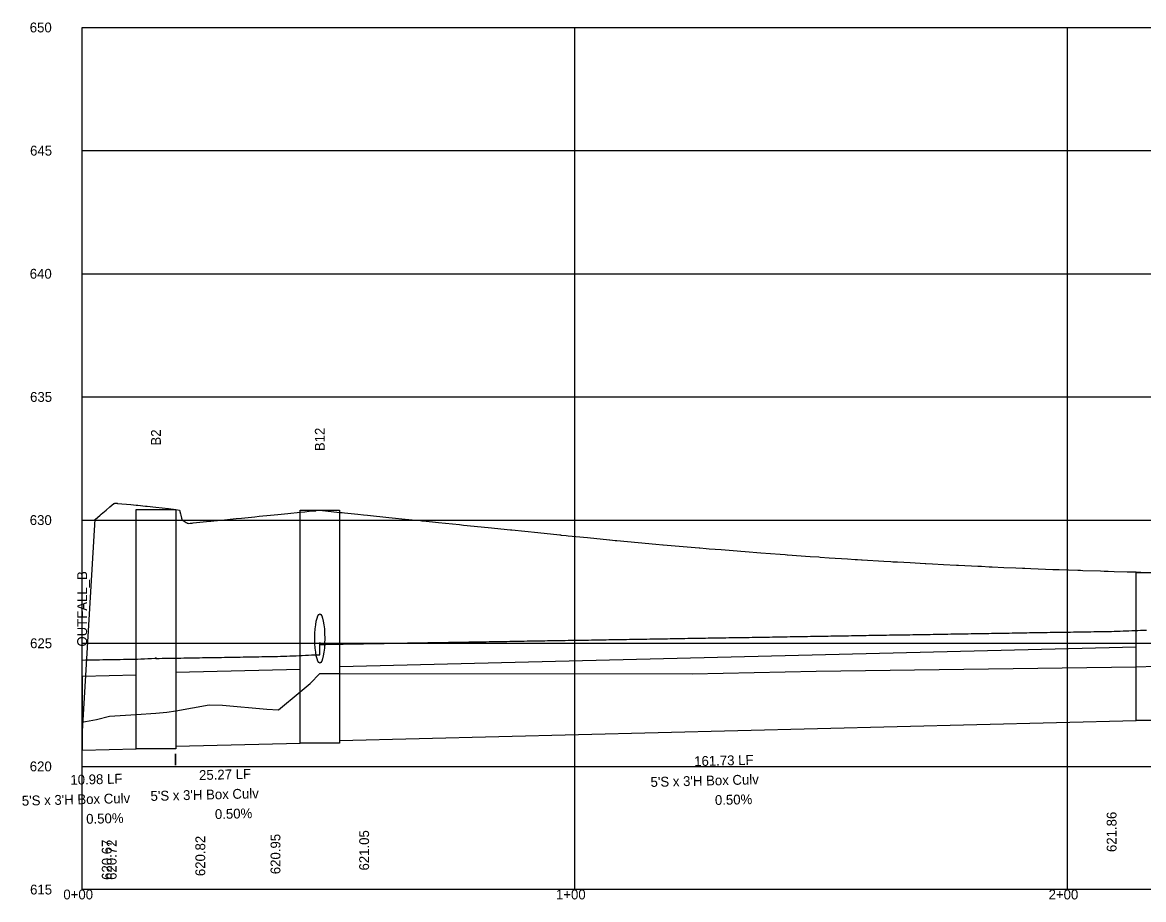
# Model space of a CAD drawing. Extents: x 2253035 to 2279930, y 13774972 to 13793443.
# Drawn here: x 2260014.3 to 2260241.9, y 13791296.5 to 13791474.6 of the extents above; entities that cross this region are included whole.
import ezdxf

# ---------------------------------------------------------------- set-up
doc = ezdxf.new("R2010")
doc.units = 0
for name, color, linetype in [('Default', 7, 'Continuous'), ('E_Utility_ATT_HH', 7, 'Continuous'), ('E_Utility_ATT_PR_PVC', 7, 'Continuous'), ('E_Utillity_Water_Water Line_12in', 7, 'Continuous'), ('E_Utillity_Water_Water Line_1in', 7, 'Continuous'), ('E_Utillity_Water_Water Line_4in', 7, 'Continuous'), ('E_Utillity_Water_Water Line_8in', 7, 'Continuous')]:
    doc.layers.add(name, color=color, linetype=linetype)

msp = doc.modelspace()

# ---------------------------------------------------------------- linework, layer by layer
at = {"layer": 'Default'}
for p, q in [((2260126.46, 13791298.56), (2260126.46, 13791473.56)), ((2260226.46, 13791298.56), (2260226.46, 13791473.56)), ((2260026.46, 13791448.56), (2261320.64, 13791448.56)), ((2260026.46, 13791423.56), (2261320.64, 13791423.56)), ((2260026.46, 13791398.56), (2261320.64, 13791398.56)), ((2260026.46, 13791373.56), (2261320.64, 13791373.56)), ((2260026.46, 13791348.56), (2261320.64, 13791348.56)), ((2260026.46, 13791323.56), (2261320.64, 13791323.56))]:
    msp.add_line(p, q, dxfattribs=at)
msp.add_lwpolyline([(2260026.46, 13791298.56), (2260026.46, 13791473.56), (2261320.64, 13791473.56), (2261320.64, 13791298.56)], close=True, dxfattribs=at)
at = {"layer": 'E_Utility_ATT_PR_PVC'}
for p, q in [((2260074.71, 13791348.72), (2260074.71, 13791348.32)), ((2260041.45, 13791345.68), (2260041.45, 13791345.48))]:
    msp.add_line(p, q, dxfattribs=at)
for points in [[(2260074.71, 13791348.32), (2260075.31, 13791348.33), (2260075.9, 13791348.34), (2260076.49, 13791348.35), (2260077.09, 13791348.36), (2260077.68, 13791348.37), (2260078.27, 13791348.38), (2260078.86, 13791348.39), (2260079.46, 13791348.4), (2260080.05, 13791348.41), (2260080.64, 13791348.42), (2260081.24, 13791348.43), (2260081.83, 13791348.44), (2260082.42, 13791348.45), (2260083.01, 13791348.46), (2260083.61, 13791348.47), (2260084.2, 13791348.48), (2260084.79, 13791348.49), (2260085.39, 13791348.5), (2260085.98, 13791348.51), (2260086.57, 13791348.52), (2260087.16, 13791348.53), (2260087.76, 13791348.54), (2260088.35, 13791348.55), (2260088.94, 13791348.56), (2260089.54, 13791348.57), (2260090.13, 13791348.58), (2260090.72, 13791348.59), (2260091.32, 13791348.6), (2260091.91, 13791348.61), (2260092.5, 13791348.62), (2260093.09, 13791348.62), (2260093.69, 13791348.63), (2260094.28, 13791348.64), (2260094.87, 13791348.65), (2260095.47, 13791348.66), (2260096.06, 13791348.67), (2260096.65, 13791348.68), (2260097.24, 13791348.69), (2260097.84, 13791348.7), (2260098.43, 13791348.71), (2260099.02, 13791348.72), (2260099.62, 13791348.73), (2260100.21, 13791348.74), (2260100.8, 13791348.75), (2260101.39, 13791348.76), (2260101.99, 13791348.77), (2260102.58, 13791348.78), (2260103.17, 13791348.79), (2260103.77, 13791348.8), (2260104.36, 13791348.81), (2260104.95, 13791348.82), (2260105.55, 13791348.83), (2260106.14, 13791348.84), (2260106.73, 13791348.85), (2260107.32, 13791348.86), (2260107.92, 13791348.87), (2260108.51, 13791348.88), (2260109.1, 13791348.89), (2260109.7, 13791348.9), (2260110.29, 13791348.91), (2260110.88, 13791348.92), (2260111.47, 13791348.93), (2260112.07, 13791348.94), (2260112.66, 13791348.95), (2260113.25, 13791348.96), (2260113.85, 13791348.97), (2260114.44, 13791348.98), (2260115.03, 13791348.99), (2260115.62, 13791349), (2260116.22, 13791349.01), (2260116.81, 13791349.02), (2260117.4, 13791349.03), (2260118, 13791349.04), (2260118.59, 13791349.05), (2260119.18, 13791349.06), (2260119.78, 13791349.07), (2260120.37, 13791349.08), (2260120.96, 13791349.09), (2260121.55, 13791349.1), (2260122.15, 13791349.11), (2260122.74, 13791349.12), (2260123.33, 13791349.13), (2260123.93, 13791349.14), (2260124.52, 13791349.15), (2260125.11, 13791349.16), (2260125.7, 13791349.17), (2260126.3, 13791349.17), (2260126.89, 13791349.18), (2260127.48, 13791349.19), (2260128.08, 13791349.2), (2260128.67, 13791349.21), (2260129.26, 13791349.22), (2260129.85, 13791349.23), (2260130.45, 13791349.24), (2260131.04, 13791349.25), (2260131.63, 13791349.26), (2260132.23, 13791349.27), (2260132.82, 13791349.28), (2260133.41, 13791349.29), (2260134.01, 13791349.3), (2260134.6, 13791349.31), (2260135.19, 13791349.32), (2260135.78, 13791349.33), (2260136.38, 13791349.34), (2260136.97, 13791349.35), (2260137.56, 13791349.36), (2260138.16, 13791349.37), (2260138.75, 13791349.38), (2260139.34, 13791349.39), (2260139.93, 13791349.4), (2260140.53, 13791349.41), (2260141.12, 13791349.42), (2260141.71, 13791349.43), (2260142.31, 13791349.44), (2260142.9, 13791349.45), (2260143.49, 13791349.46), (2260144.08, 13791349.47), (2260144.68, 13791349.48), (2260145.27, 13791349.49), (2260145.86, 13791349.5), (2260146.46, 13791349.51), (2260147.05, 13791349.52), (2260147.64, 13791349.53), (2260148.24, 13791349.54), (2260148.83, 13791349.55), (2260149.42, 13791349.56), (2260150.01, 13791349.57), (2260150.61, 13791349.58), (2260151.2, 13791349.59), (2260151.79, 13791349.6), (2260152.39, 13791349.61), (2260152.98, 13791349.62), (2260153.57, 13791349.63), (2260154.16, 13791349.64), (2260154.76, 13791349.65), (2260155.35, 13791349.66), (2260155.94, 13791349.67), (2260156.54, 13791349.68), (2260157.13, 13791349.69), (2260157.72, 13791349.7), (2260158.31, 13791349.71), (2260158.91, 13791349.72), (2260159.5, 13791349.73), (2260160.09, 13791349.73), (2260160.69, 13791349.74), (2260161.28, 13791349.75), (2260161.87, 13791349.76), (2260162.47, 13791349.77), (2260163.06, 13791349.78), (2260163.65, 13791349.79), (2260164.24, 13791349.8), (2260164.84, 13791349.81), (2260165.43, 13791349.82), (2260166.02, 13791349.83), (2260166.62, 13791349.84), (2260167.21, 13791349.85), (2260167.8, 13791349.86), (2260168.39, 13791349.87), (2260168.99, 13791349.88), (2260169.58, 13791349.89), (2260170.17, 13791349.9), (2260170.77, 13791349.91), (2260171.36, 13791349.92), (2260171.95, 13791349.93), (2260172.54, 13791349.94), (2260173.14, 13791349.95), (2260173.73, 13791349.96), (2260174.32, 13791349.97), (2260174.92, 13791349.98), (2260175.51, 13791349.99), (2260176.1, 13791350), (2260176.7, 13791350.01), (2260177.29, 13791350.02), (2260177.88, 13791350.03), (2260178.47, 13791350.04), (2260179.07, 13791350.05), (2260179.66, 13791350.06), (2260180.25, 13791350.07), (2260180.85, 13791350.08), (2260181.44, 13791350.09), (2260182.03, 13791350.1), (2260182.62, 13791350.11), (2260183.22, 13791350.12), (2260183.81, 13791350.13), (2260184.4, 13791350.14), (2260185, 13791350.15), (2260185.59, 13791350.16), (2260186.18, 13791350.17), (2260186.77, 13791350.18), (2260187.37, 13791350.19), (2260187.96, 13791350.2), (2260188.55, 13791350.21), (2260189.15, 13791350.22), (2260189.74, 13791350.23), (2260190.33, 13791350.24), (2260190.93, 13791350.25), (2260191.52, 13791350.26), (2260192.11, 13791350.27), (2260192.7, 13791350.28), (2260193.3, 13791350.28), (2260193.89, 13791350.29), (2260194.48, 13791350.3), (2260195.08, 13791350.31), (2260195.67, 13791350.32), (2260196.26, 13791350.33), (2260196.85, 13791350.34), (2260197.45, 13791350.35), (2260198.04, 13791350.36), (2260198.63, 13791350.37), (2260199.23, 13791350.38), (2260199.82, 13791350.39), (2260200.41, 13791350.4), (2260201, 13791350.41), (2260201.6, 13791350.42), (2260202.19, 13791350.43), (2260202.78, 13791350.44), (2260203.38, 13791350.45), (2260203.97, 13791350.46), (2260204.56, 13791350.47), (2260205.16, 13791350.48), (2260205.75, 13791350.49), (2260206.34, 13791350.5), (2260206.93, 13791350.51), (2260207.53, 13791350.52), (2260208.12, 13791350.53), (2260208.71, 13791350.54), (2260209.31, 13791350.55), (2260209.9, 13791350.56), (2260210.49, 13791350.57), (2260211.08, 13791350.58), (2260211.68, 13791350.59), (2260212.27, 13791350.6), (2260212.86, 13791350.61), (2260213.46, 13791350.62), (2260214.05, 13791350.63), (2260214.64, 13791350.64), (2260215.23, 13791350.65), (2260215.83, 13791350.66), (2260216.42, 13791350.67), (2260217.01, 13791350.68), (2260217.61, 13791350.69), (2260218.2, 13791350.7), (2260218.79, 13791350.71), (2260219.39, 13791350.72), (2260219.98, 13791350.73), (2260220.57, 13791350.74), (2260221.16, 13791350.75), (2260221.76, 13791350.76), (2260222.35, 13791350.77), (2260222.94, 13791350.78), (2260223.54, 13791350.79), (2260224.13, 13791350.8), (2260224.72, 13791350.81), (2260225.31, 13791350.82), (2260225.91, 13791350.83), (2260226.5, 13791350.84), (2260227.09, 13791350.84), (2260227.69, 13791350.85), (2260228.28, 13791350.86), (2260228.87, 13791350.87), (2260229.46, 13791350.88), (2260230.06, 13791350.89), (2260230.65, 13791350.9), (2260231.24, 13791350.91), (2260231.84, 13791350.92), (2260232.43, 13791350.93), (2260233.02, 13791350.94), (2260233.62, 13791350.95), (2260234.21, 13791350.96), (2260234.8, 13791350.97), (2260235.39, 13791350.98), (2260235.99, 13791350.99), (2260236.58, 13791351.01), (2260237.17, 13791351.03), (2260237.77, 13791351.05), (2260238.36, 13791351.08), (2260238.95, 13791351.1), (2260239.54, 13791351.13), (2260240.14, 13791351.15), (2260240.73, 13791351.18), (2260241.32, 13791351.2), (2260241.92, 13791351.23), (2260242.51, 13791351.25)], [(2260041.45, 13791345.48), (2260042.08, 13791345.49), (2260042.71, 13791345.5), (2260043.34, 13791345.51), (2260043.97, 13791345.52), (2260044.61, 13791345.53), (2260045.24, 13791345.54), (2260045.87, 13791345.55), (2260046.5, 13791345.56), (2260047.13, 13791345.58), (2260047.76, 13791345.59), (2260048.4, 13791345.6), (2260049.03, 13791345.61), (2260049.66, 13791345.62), (2260050.29, 13791345.63), (2260050.92, 13791345.64), (2260051.56, 13791345.65), (2260052.19, 13791345.66), (2260052.82, 13791345.67), (2260053.45, 13791345.68), (2260054.08, 13791345.69), (2260054.72, 13791345.7), (2260055.35, 13791345.72), (2260055.98, 13791345.73), (2260056.61, 13791345.74), (2260057.24, 13791345.75), (2260057.88, 13791345.76), (2260058.51, 13791345.77), (2260059.14, 13791345.78), (2260059.77, 13791345.79), (2260060.4, 13791345.8), (2260061.04, 13791345.81), (2260061.67, 13791345.82), (2260062.3, 13791345.83), (2260062.93, 13791345.84), (2260063.56, 13791345.86), (2260064.19, 13791345.87), (2260064.83, 13791345.88), (2260065.46, 13791345.89), (2260066.09, 13791345.9), (2260066.72, 13791345.91), (2260067.35, 13791345.94), (2260067.99, 13791345.96), (2260068.62, 13791345.99), (2260069.25, 13791346.02), (2260069.88, 13791346.04), (2260070.51, 13791346.07), (2260071.15, 13791346.1), (2260071.78, 13791346.12), (2260072.41, 13791346.15), (2260073.04, 13791346.18), (2260073.67, 13791346.2), (2260074.31, 13791346.23), (2260074.71, 13791346.24), (2260074.71, 13791348.72)], [(2260026.46, 13791345.16), (2260027.16, 13791345.17), (2260027.86, 13791345.18), (2260028.57, 13791345.19), (2260029.27, 13791345.21), (2260029.97, 13791345.22), (2260030.68, 13791345.23), (2260031.38, 13791345.24), (2260032.08, 13791345.26), (2260032.78, 13791345.27), (2260033.49, 13791345.28), (2260034.19, 13791345.29), (2260034.89, 13791345.31), (2260035.6, 13791345.32), (2260036.3, 13791345.33), (2260037, 13791345.35), (2260037.71, 13791345.36), (2260038.41, 13791345.39), (2260039.11, 13791345.42), (2260039.82, 13791345.45), (2260040.52, 13791345.49), (2260041.22, 13791345.52), (2260041.45, 13791345.52), (2260041.45, 13791345.68)]]:
    msp.add_lwpolyline(points, dxfattribs=at)
at = {"layer": 'E_Utillity_Water_Water Line_12in'}
for points in [[(2260037.45, 13791375.69), (2260045.45, 13791375.69), (2260045.45, 13791327.16), (2260037.45, 13791327.16)], [(2260070.71, 13791375.55), (2260078.71, 13791375.55), (2260078.71, 13791328.31), (2260070.71, 13791328.31)], [(2260240.44, 13791362.93), (2260248.44, 13791362.93), (2260248.44, 13791332.86), (2260240.44, 13791332.86)], [(2260026.46, 13791341.86), (2260026.46, 13791341.86), (2260026.46, 13791326.88), (2260026.46, 13791326.88)], [(2260045.41, 13791326.09), (2260045.41, 13791326.09), (2260045.41, 13791323.78), (2260045.41, 13791323.78)]]:
    msp.add_lwpolyline(points, close=True, dxfattribs=at)
at = {"layer": 'E_Utillity_Water_Water Line_1in'}
msp.add_lwpolyline([(2260026.46, 13791332.58), (2260026.46, 13791332.58), (2260026.46, 13791332.58), (2260027.15, 13791332.71), (2260029.39, 13791333.06), (2260032.04, 13791333.77), (2260037.45, 13791334.13), (2260037.45, 13791334.13), (2260041.45, 13791334.39), (2260041.45, 13791334.39), (2260043.66, 13791334.54), (2260045.45, 13791334.85), (2260045.45, 13791334.85), (2260052.27, 13791336.06), (2260054.98, 13791335.98), (2260063.97, 13791335.16), (2260066.35, 13791335.06), (2260070.71, 13791338.69), (2260070.71, 13791338.69), (2260072.75, 13791340.38), (2260074.71, 13791342.43), (2260074.71, 13791342.43), (2260078.71, 13791342.4), (2260078.71, 13791342.4), (2260150.29, 13791342.38), (2260175.47, 13791342.91), (2260240.44, 13791343.79), (2260240.44, 13791343.79), (2260244.44, 13791343.93)], dxfattribs=at)
at = {"layer": 'E_Utillity_Water_Water Line_4in'}
for p, q in [((2260078.71, 13791343.81), (2260240.44, 13791347.86)), ((2260045.45, 13791342.67), (2260070.71, 13791343.31)), ((2260026.46, 13791341.88), (2260037.45, 13791342.16)), ((2260078.71, 13791328.81), (2260240.44, 13791332.86)), ((2260026.46, 13791326.88), (2260037.45, 13791327.16)), ((2260045.45, 13791327.67), (2260070.71, 13791328.31))]:
    msp.add_line(p, q, dxfattribs=at)
msp.add_ellipse((2260074.71, 13791349.53), major_axis=(0, 5), ratio=0.2, dxfattribs=at)
at = {"layer": 'E_Utillity_Water_Water Line_8in'}
msp.add_lwpolyline([(2260026.46, 13791329.56), (2260026.46, 13791329.56), (2260026.46, 13791329.56), (2260029.12, 13791373.73), (2260029.12, 13791373.73), (2260029.15, 13791373.75), (2260029.17, 13791373.77), (2260029.56, 13791374.1), (2260030.11, 13791374.56), (2260030.34, 13791374.75), (2260031.31, 13791375.56), (2260032.11, 13791376.22), (2260032.51, 13791376.56), (2260032.92, 13791376.9), (2260032.98, 13791376.95), (2260033, 13791376.96), (2260033.06, 13791377.02), (2260033.54, 13791376.97), (2260033.64, 13791376.96), (2260036.34, 13791376.7), (2260037.45, 13791376.59), (2260037.45, 13791376.59), (2260037.79, 13791376.56), (2260039.34, 13791376.4), (2260039.54, 13791376.38), (2260039.68, 13791376.36), (2260041.42, 13791376.18), (2260041.45, 13791376.18), (2260041.45, 13791376.18), (2260042.69, 13791376.05), (2260044.01, 13791375.91), (2260045.45, 13791375.69), (2260045.45, 13791375.69), (2260046.25, 13791375.56), (2260046.43, 13791374.85), (2260046.51, 13791374.56), (2260046.66, 13791373.98), (2260046.71, 13791373.78), (2260046.77, 13791373.56), (2260046.92, 13791373.47), (2260047.19, 13791373.31), (2260047.59, 13791373.08), (2260047.73, 13791373), (2260047.73, 13791373), (2260047.8, 13791372.96), (2260047.85, 13791372.93), (2260047.86, 13791372.93), (2260047.89, 13791372.91), (2260047.96, 13791372.87), (2260048.41, 13791372.92), (2260048.5, 13791372.93), (2260048.8, 13791372.96), (2260048.83, 13791372.96), (2260049.01, 13791372.98), (2260052.4, 13791373.32), (2260052.51, 13791373.33), (2260052.57, 13791373.34), (2260053.22, 13791373.4), (2260054.76, 13791373.56), (2260057.75, 13791373.86), (2260058.8, 13791373.96), (2260061.52, 13791374.24), (2260062.43, 13791374.33), (2260064.71, 13791374.56), (2260066.21, 13791374.71), (2260068.22, 13791374.91), (2260070.71, 13791375.16), (2260070.71, 13791375.16), (2260071.64, 13791375.25), (2260072.55, 13791375.34), (2260073.57, 13791375.44), (2260073.9, 13791375.47), (2260073.97, 13791375.48), (2260074.71, 13791375.55), (2260074.71, 13791375.55), (2260078.71, 13791375.13), (2260078.71, 13791375.13), (2260079.28, 13791375.08), (2260079.71, 13791375.03), (2260082.43, 13791374.75), (2260083.59, 13791374.64), (2260084.36, 13791374.56), (2260088.74, 13791374.11), (2260092.74, 13791373.7), (2260092.76, 13791373.7), (2260094.13, 13791373.56), (2260095.15, 13791373.45), (2260095.44, 13791373.42), (2260095.67, 13791373.4), (2260098.83, 13791373.08), (2260103.08, 13791372.64), (2260103.9, 13791372.56), (2260108.89, 13791372.05), (2260113.4, 13791371.59), (2260113.68, 13791371.56), (2260118.95, 13791371.02), (2260123.45, 13791370.56), (2260123.59, 13791370.54), (2260123.68, 13791370.53), (2260124.73, 13791370.43), (2260125.12, 13791370.39), (2260129.04, 13791370), (2260133.54, 13791369.56), (2260133.57, 13791369.55), (2260133.59, 13791369.55), (2260134.69, 13791369.45), (2260135.02, 13791369.42), (2260139.34, 13791369.01), (2260142.91, 13791368.69), (2260142.91, 13791368.69), (2260142.93, 13791368.69), (2260144.34, 13791368.56), (2260144.39, 13791368.56), (2260149.26, 13791368.13), (2260151.75, 13791367.92), (2260151.86, 13791367.91), (2260153.16, 13791367.8), (2260153.73, 13791367.76), (2260156.17, 13791367.56), (2260159.42, 13791367.29), (2260160.17, 13791367.24), (2260161.03, 13791367.17), (2260164.21, 13791366.92), (2260168.17, 13791366.63), (2260169.15, 13791366.56), (2260169.55, 13791366.53), (2260169.64, 13791366.52), (2260174.23, 13791366.2), (2260175.98, 13791366.08), (2260176.25, 13791366.06), (2260178.1, 13791365.93), (2260181.8, 13791365.69), (2260183.39, 13791365.59), (2260183.87, 13791365.56), (2260184.67, 13791365.51), (2260184.82, 13791365.5), (2260189.21, 13791365.23), (2260190.64, 13791365.15), (2260191, 13791365.12), (2260192, 13791365.07), (2260194.55, 13791364.92), (2260197.61, 13791364.75), (2260197.62, 13791364.75), (2260197.73, 13791364.74), (2260199.05, 13791364.67), (2260201.29, 13791364.56), (2260203.97, 13791364.42), (2260204.37, 13791364.4), (2260208.27, 13791364.21), (2260209.02, 13791364.18), (2260210.58, 13791364.1), (2260210.93, 13791364.09), (2260211.22, 13791364.07), (2260213.59, 13791363.97), (2260216.02, 13791363.86), (2260217.33, 13791363.81), (2260217.81, 13791363.79), (2260219.05, 13791363.74), (2260223.54, 13791363.56), (2260223.7, 13791363.56), (2260224.69, 13791363.52), (2260224.79, 13791363.52), (2260228.59, 13791363.38), (2260229.11, 13791363.37), (2260229.63, 13791363.35), (2260233.17, 13791363.23), (2260233.92, 13791363.21), (2260234.35, 13791363.2), (2260234.73, 13791363.19), (2260235.96, 13791363.15), (2260238.59, 13791363.07), (2260240.24, 13791363.03), (2260240.44, 13791363.03), (2260240.44, 13791363.03), (2260241.36, 13791363), (2260243.52, 13791362.95)], dxfattribs=at)

# ---------------------------------------------------------------- texts
at = {"layer": 'Default'}
for s, p in [('650', (2260015.83, 13791472.56)), ('645', (2260015.9, 13791447.56)), ('640', (2260015.83, 13791422.56)), ('635', (2260015.9, 13791397.56)), ('630', (2260015.83, 13791372.56)), ('625', (2260015.9, 13791347.56)), ('620', (2260015.83, 13791322.56)), ('615', (2260015.9, 13791297.56)), ('0+00', (2260022.65, 13791296.56)), ('1+00', (2260122.65, 13791296.56)), ('2+00', (2260222.65, 13791296.56))]:
    msp.add_text(s, height=2, dxfattribs=at).set_placement(p)
at = {"layer": 'E_Utility_ATT_HH'}
for s, rotation, p in [('B2', 90, (2260042.45, 13791388.69)), ('B12', 90, (2260075.71, 13791387.56)), ('OUTFALL_B', 90, (2260027.46, 13791347.88)), ('161.73 LF', 1.4321, (2260150.73, 13791323.61)), ('25.27 LF', 1.4321, (2260050.22, 13791320.79)), ('10.98 LF', 1.4321, (2260024.1, 13791319.82)), ("5'S x 3'H Box Culv", 1.4321, (2260141.87, 13791319.39)), ("5'S x 3'H Box Culv", 1.4321, (2260014.25, 13791315.58)), ("5'S x 3'H Box Culv", 1.4321, (2260040.37, 13791316.55)), ('0.50%', 1.4321, (2260154.94, 13791315.72)), ('0.50%', 1.4321, (2260027.31, 13791311.9)), ('0.50%', 1.4321, (2260053.44, 13791312.87)), ('621.86', 90, (2260236.44, 13791306.18)), ('620.67', 90, (2260032.46, 13791300.52)), ('620.72', 90, (2260033.45, 13791300.53)), ('620.82', 90, (2260051.45, 13791301.29)), ('620.95', 90, (2260066.71, 13791301.68)), ('621.05', 90, (2260084.71, 13791302.43))]:
    msp.add_text(s, height=2, rotation=rotation, dxfattribs=at).set_placement(p)

doc.saveas('drawing.dxf')
